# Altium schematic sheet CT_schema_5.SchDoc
size 296 x 258 mm
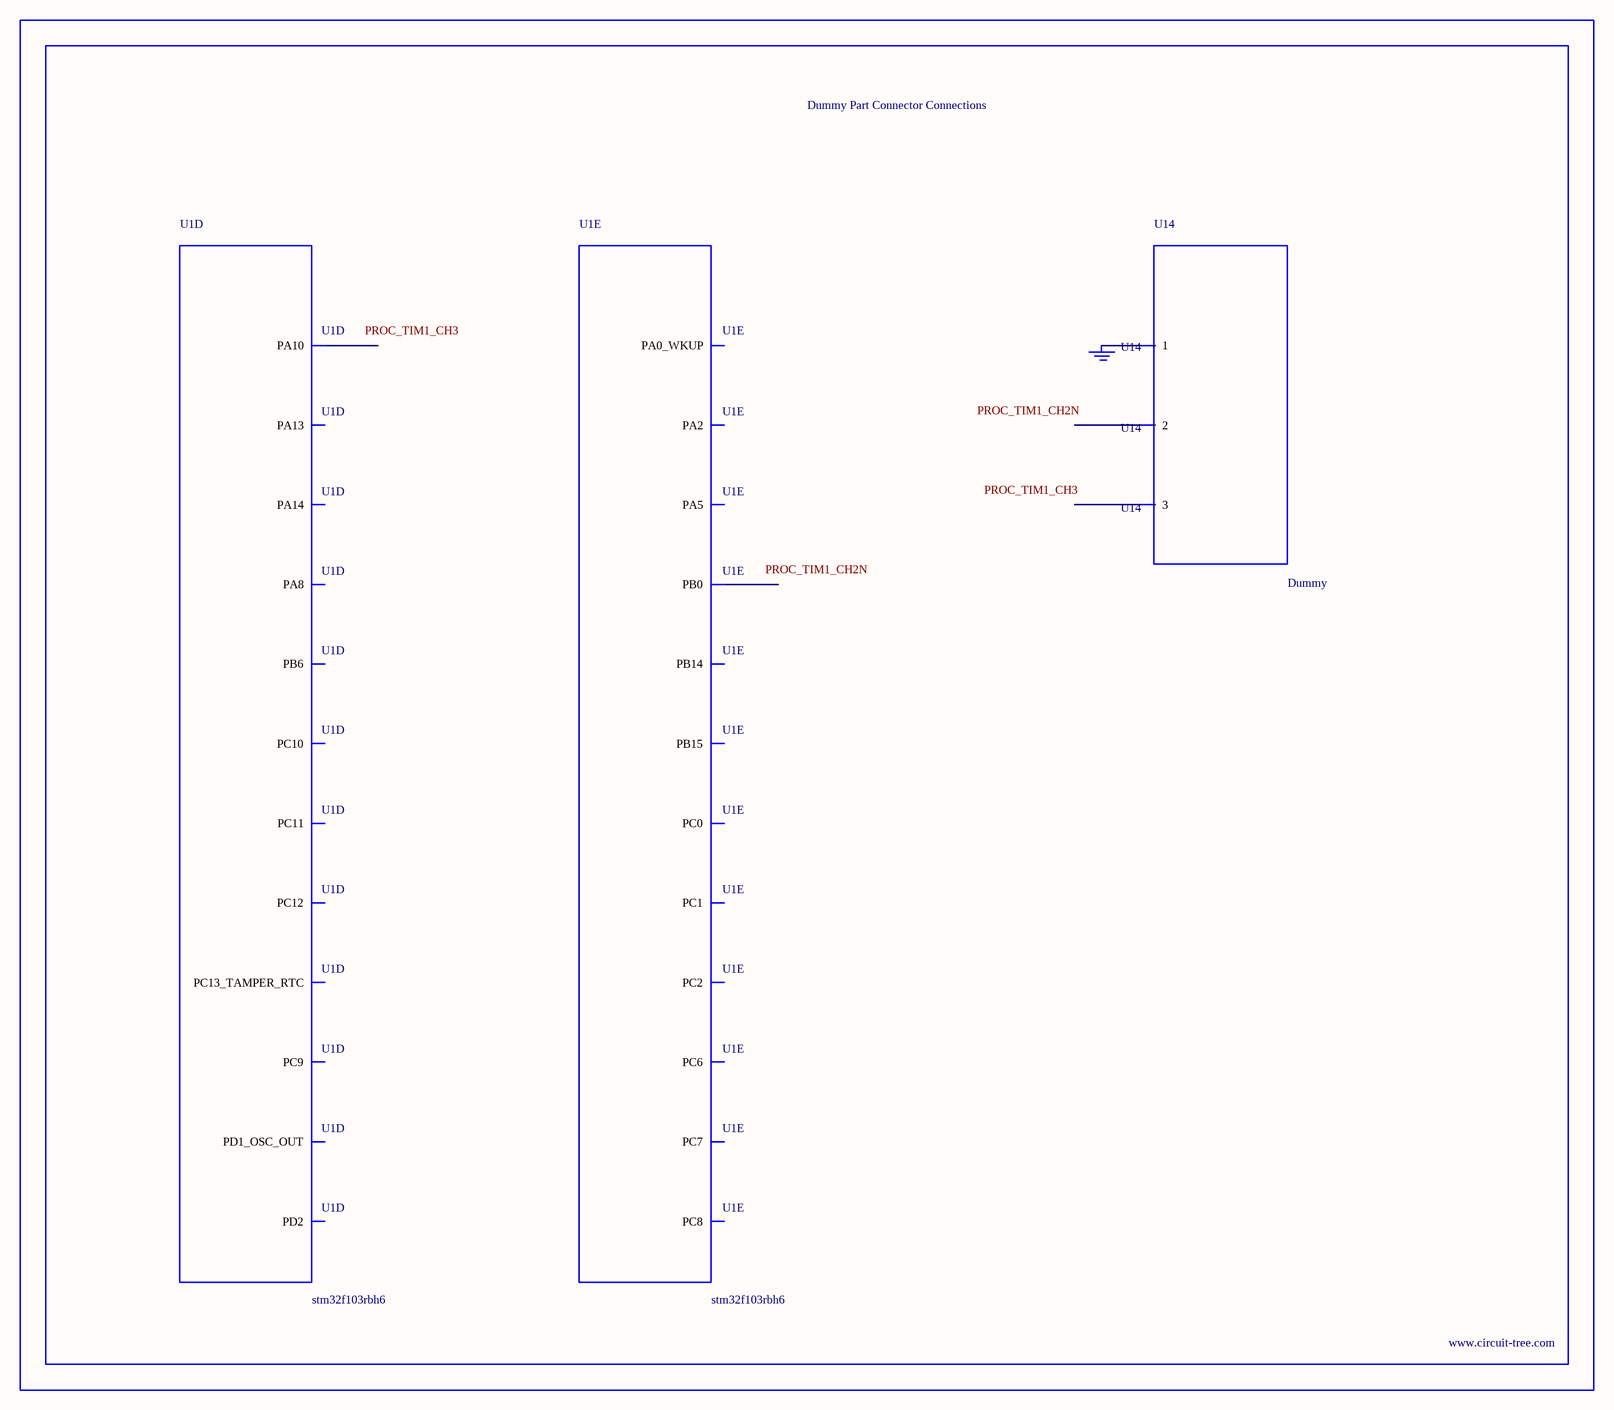
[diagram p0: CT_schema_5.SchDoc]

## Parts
BORDER4  (no value)
GND_INSTANCE_4_0  (no value)
U1  stm32f103rbh6  [TFBGA64]  (parts D,E of 5)
U14  Dummy  [DUMMY_PACKAGE_127]

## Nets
NetGND_INSTANCE_4_0_0: GND_INSTANCE_4_0.0(GND) U14.1

Not connected (* = marked no-connect by the designer): U1 A2(PC13_TAMPER_RTC) A7(PA14) A8(PA13) B5(PD2) B6(PC11) B7(PC10) C5(PC12) C6(PA10) D1(PD1_OSC_OUT) D3(PB6) D7(PA8) D8(PC9) E2(PC1) E3(PC0) E7(PC7) E8(PC8) F2(PC2) F3(PA2) F4(PA5) F5(PB0) F6(PC6) F7(PB15) F8(PB14) G2(PA0_WKUP); U14 2 3

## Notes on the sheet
- Labels drawn without touching a wire or pin: PROC_TIM1_CH2N, PROC_TIM1_CH3

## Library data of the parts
BORDER4 = BORDER_PAGE4
GND_INSTANCE_4_0 = GND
